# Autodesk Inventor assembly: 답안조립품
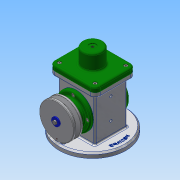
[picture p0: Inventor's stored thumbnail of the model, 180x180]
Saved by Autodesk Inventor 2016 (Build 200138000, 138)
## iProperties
Created: 2019-08
Part Number: 답안조립품
Material: 일반
Document SubType Name: Assembly
Designer: 605-15
Author: 605-15
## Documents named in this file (18)
- C:\Users\605-15\Desktop\490804V1021\답안조립품.iam
- C:\Users\605-15\Desktop\490804V1021\본체.ipt
- C:\Users\605-15\Desktop\490804V1021\뒤커버.ipt
- C:\Users\605-15\Desktop\490804V1021\앞커버.ipt
- C:\Users\605-15\Desktop\490804V1021\오일 실 17 30 8.ipt
- C:\Users\605-15\Desktop\490804V1021\베어링 17 x 40 x 12.ipt
- C:\Users\605-15\Desktop\490804V1021\E-링.ipt
- C:\Users\605-15\Desktop\490804V1021\링크.ipt
- C:\Users\605-15\Desktop\490804V1021\슬라이더.ipt
- C:\Users\605-15\Desktop\490804V1021\클레비스 핀 6 x 22.ipt
- 클레비스 핀 6 x 22.ipt
- C:\Users\605-15\Desktop\490804V1021\편심축.ipt
- C:\Users\605-15\Desktop\490804V1021\덮개.ipt
- C:\Users\605-15\Desktop\490804V1021\V-벨트풀리.ipt
- C:\Users\605-15\Desktop\490804V1021\키 4 x 4 x 12.ipt
- C:\Users\605-15\Desktop\490804V1021\볼트 M4 x 10.ipt
- C:\Users\605-15\Desktop\490804V1021\와셔 4x16.ipt
- C:\Users\605-15\Desktop\490804V1021\볼트 M4 x 8.ipt
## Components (2 placed, 2 different names)
1. E-링:1
2. V-벨트풀리:1
